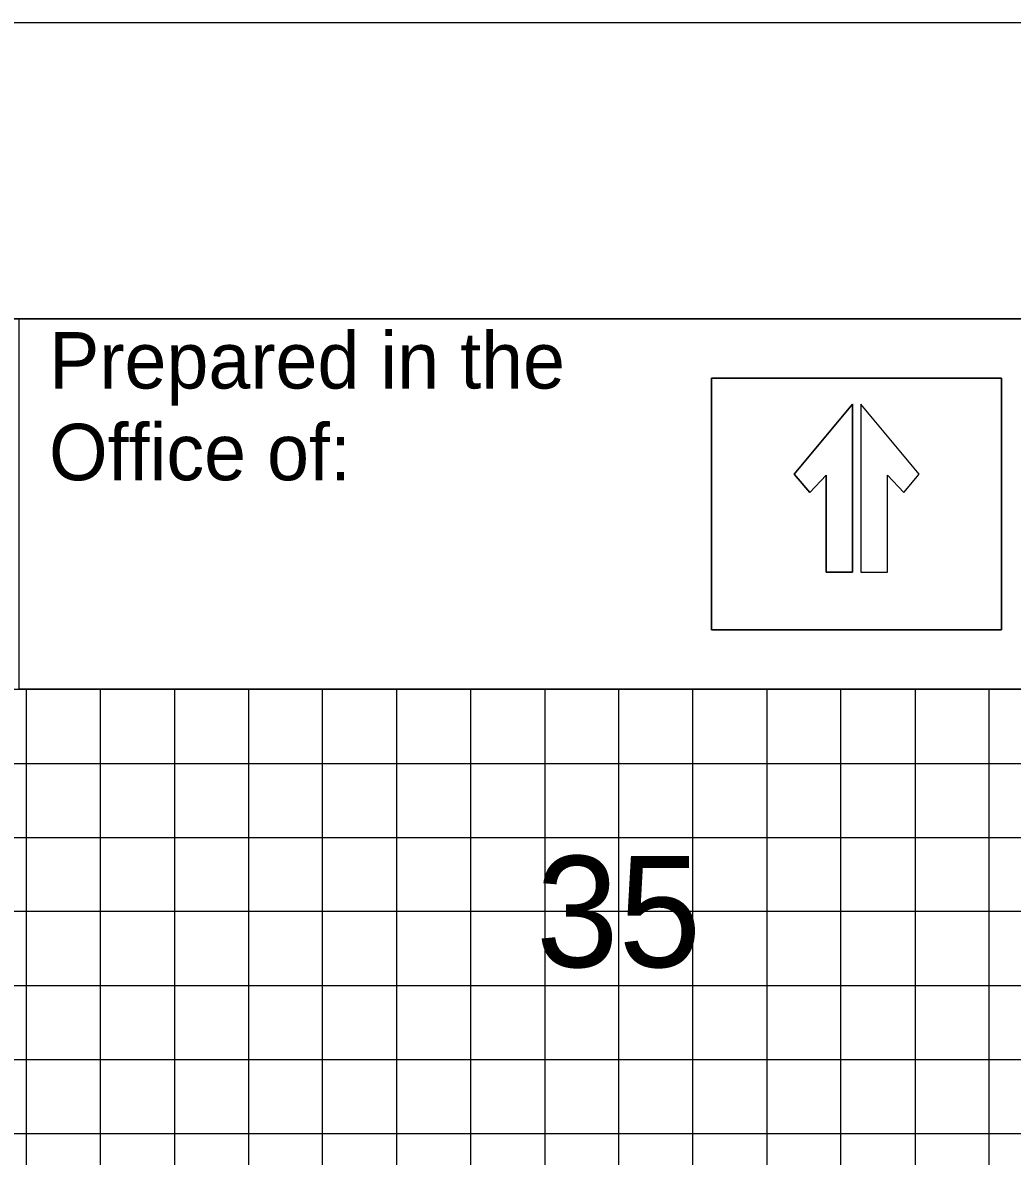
# Model space of a CAD drawing. Extents: x -7 to 162, y -2 to 217.
# Drawn here: x 110.98 to 117.66, y 99.35 to 107 of the extents above; entities that cross this region are included whole.
import ezdxf

# ---------------------------------------------------------------- set-up
doc = ezdxf.new("R2010")
doc.units = 0
for name, color, linetype in [('Exist Cross Section Cell', 7, 'Continuous'), ('Prop CMT Pvmt Course 2', 7, 'Continuous'), ('Prop CMT Pvmt Course 2 Wedge', 7, 'Continuous'), ('Prop CMT Pvmt Course 3', 7, 'Continuous'), ('Prop CMT Pvmt Surface', 7, 'Continuous'), ('Prop CMT Shld Paved Course 1', 7, 'Continuous'), ('Prop CMT Shld Paved Course 2', 7, 'Continuous'), ('Prop CMT Shld Paved Course 3', 7, 'Continuous'), ('Prop CMT Subgrade Earthwork', 7, 'Continuous'), ('Prop XS Side Slope Text', 7, 'Continuous'), ('Scratch_Level_3', 7, 'Continuous')]:
    doc.layers.add(name, color=color, linetype=linetype)

msp = doc.modelspace()

# ---------------------------------------------------------------- linework, layer by layer
at = {"layer": 'Prop CMT Pvmt Course 2'}
msp.add_line((0, 102), (160, 102), dxfattribs=at)
for points in [[(0, 101.5), (135, 101.5), (160, 101.5)], [(160, 101), (0, 101)], [(0, 100.5), (160, 100.5)], [(160, 99.5), (0, 99.5)]]:
    msp.add_lwpolyline(points, dxfattribs=at)
at = {"layer": 'Prop CMT Pvmt Course 3'}
for p, q in [((115, 105), (110, 105)), ((115, 0), (115, 102.5))]:
    msp.add_line(p, q, dxfattribs=at)
msp.add_lwpolyline([(0, 100), (160, 100)], dxfattribs=at)
at = {"layer": 'Prop CMT Pvmt Surface'}
msp.add_lwpolyline([(110.9512, 105), (130, 105), (130, 102.5), (110.9512, 102.5)], close=True, dxfattribs=at)
at = {"layer": 'Prop CMT Shld Paved Course 1'}
msp.add_lwpolyline([(-6.7, -2.5), (161.65, -2.5), (161.65, 107), (-6.7, 107)], close=True, dxfattribs=at)
at = {"layer": 'Prop CMT Shld Paved Course 2'}
msp.add_lwpolyline([(-5.4, -0.5), (161.2, -0.5), (161.2, 105), (-5.4, 105)], close=True, dxfattribs=at)
at = {"layer": 'Prop CMT Shld Paved Course 3'}
for points in [[(72.5, 0), (77.5, 0), (77.5, 105), (82.5, 105), (82.5, 0), (87.5, 0), (87.5, 105), (92.5, 105), (92.5, 0), (97.5, 0), (97.5, 105), (102.5, 105), (102.5, 0), (107.5, 0), (107.5, 105), (112.5, 105)], [(117.5, 105), (122.5, 105)], [(0, 102.5), (137.5, 102.5)], [(112.5, 102.5), (112.5, 0), (117.5, 0), (117.5, 102.5)]]:
    msp.add_lwpolyline(points, dxfattribs=at)
at = {"layer": 'Prop CMT Subgrade Earthwork'}
for points in [[(110, 0), (110.5, 0), (110.5, 105), (111, 105)], [(111.5, 105), (112, 105)], [(113, 105), (113.5, 105)], [(114, 105), (114.5, 105)], [(115.5, 105), (116, 105)], [(116.5, 105), (117, 105)], [(111, 102.5), (111, 0)], [(111, 0), (111.5, 0), (111.5, 102.5)], [(112, 102.5), (112, 0)], [(112.5, 0), (113, 0), (113, 102.5)], [(113.5, 102.5), (113.5, 0)], [(113.5, 0), (114, 0), (114, 102.5)], [(114.5, 102.5), (114.5, 0)], [(115, 0), (115.5, 0), (115.5, 102.5)], [(116, 102.5), (116, 0)], [(116, 0), (116.5, 0), (116.5, 102.5)], [(117, 102.5), (117, 0)]]:
    msp.add_lwpolyline(points, dxfattribs=at)
at = {"layer": 'Prop XS Side Slope Text'}
for points in [[(117.584, 104.5995), (115.6266, 104.5995), (115.6266, 102.9005), (117.584, 102.9005), (117.584, 104.5995)], [(116.5788, 104.4257), (116.5788, 103.2897), (116.3999, 103.2897), (116.3999, 103.945), (116.2891, 103.8276), (116.1849, 103.9521), (116.5788, 104.4257)], [(116.1849, 103.9521), (116.2891, 103.8276), (116.3999, 103.945), (116.3999, 103.2897), (116.5788, 103.2897), (116.5788, 104.4257), (116.1849, 103.9521)], [(116.6339, 104.4257), (116.6339, 103.2897), (116.8129, 103.2897), (116.8129, 103.945), (116.9237, 103.8276), (117.0279, 103.9521), (116.6339, 104.4257)]]:
    msp.add_lwpolyline(points, dxfattribs=at)
for points in [[(115.6266, 104.5995), (117.584, 104.5995), (117.584, 102.9005), (115.6266, 102.9005)], [(116.6339, 104.4257), (116.6339, 103.2897), (116.8129, 103.2897), (116.8129, 103.945), (116.9237, 103.8276), (117.0279, 103.9521)]]:
    msp.add_lwpolyline(points, close=True, dxfattribs=at)
at = {"layer": 'Scratch_Level_3'}
msp.add_lwpolyline([(160, 105), (0, 105), (0, 0), (160, 0)], close=True, dxfattribs=at)

# ---------------------------------------------------------------- texts
at = {"layer": 'Exist Cross Section Cell'}
msp.add_text('35', height=0.75, dxfattribs=at).set_placement((114.4408, 100.625))
at = {"layer": 'Prop CMT Pvmt Course 2 Wedge'}
for s, height, p in [('Prepared in the ', 0.380976, (111.1533, 104.5302)), ('Office of:', 0.38098, (111.1533, 103.9112))]:
    msp.add_text(s, height=height, rotation=360, dxfattribs=at).set_placement(p)

doc.saveas('drawing.dxf')
